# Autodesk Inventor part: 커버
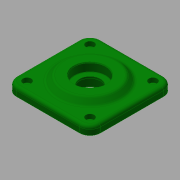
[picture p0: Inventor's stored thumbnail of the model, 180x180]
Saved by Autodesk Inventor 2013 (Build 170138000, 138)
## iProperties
Created: 2016-05
Part Number: 커버
Document SubType Name: Modeling
Designer: mduedu
Density: 2.71 g/cm^3
Material: 알루미늄 6061
Author: mduedu
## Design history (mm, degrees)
sketch "스케치1"
  geometry: L1 (-40, -40)-(40, -40); L2 (40, -40)-(40, 40); L3 (40, 40)-(-40, 40); L4 (-40, 40)-(-40, -40); L5 (-40, -40)-(40, 40); L6 (40, -40)-(-40, 40); C1 r 25 at (0, 0); 1 further point
  constraints: 12 end point, 2 midpoint, 2 parallel, 1 centre point, 1 coincident, 1 horizontal, 1 perpendicular
  dimensions: "d30" = 50 diameter of C1; "d33" = 80 distance of L3.end L2.end; "d34" = 80 distance of L2.end L1.end
extrude "돌출1" new body sketch "스케치1" distance "d0" = 8; taper "d1" = 0 deg
fillet "모깎기4" dims "d35" = 10
extrude "돌출2" join sketch "스케치1" distance "d2" = 12; taper "d3" = 0 deg
sketch "스케치2"
  geometry: C1 r 30 at (0, 0); 1 further point
  constraints: 1 centre point, 1 coincident
  dimensions: "d4" = 60 diameter of C1
extrude "돌출3" join sketch "스케치2" distance "d5" = 5; taper "d6" = -45 deg
sketch "스케치3"
  geometry: L1 (30, -40)-(-30, -40) reference; L2 (40, 30)-(40, -30) reference; L3 (-30, 40)-(30, 40) reference; L4 (-40, -30)-(-40, 30) reference; C1 r 30 at (0, 0) reference; A1 r 10 centre (-30, -30) between (-40, -30) and (-30, -40) reference; A2 r 10 centre (30, -30) between (30, -40) and (40, -30) reference; A3 r 10 centre (30, 30) between (40, 30) and (30, 40) reference; A4 r 10 centre (-30, 30) between (-30, 40) and (-40, 30) reference; 4 further points
  constraints: 4 coincident
hole "구멍2" sketch "스케치3" at (-30, 30), (30, 30), (30, -30), (-30, -30) diameter "d36" = 4.5; stored, may be unused: countersink angle "d40" = 90 deg, drill point angle "d42" = 118 deg; dims "d37" = 6, "d38" = 8, "d39" = 4.4, "d41" = 8
fillet "모깎기1" dims "d14" = 3
fillet "모깎기5" dims "d43" = 3
sketch "스케치4"
  geometry: L1 (-23.757, 13)-(23.757, 13) reference; L2 (25, -12)-(-25, -12) reference; L3 (0, -12)-(0, 13); L4 (-20, -12)-(-20, 0); L5 (-20, 0)-(-15, 0); L6 (-15, 0)-(-15, 3); L7 (-15, 3)-(-10, 3); L8 (-10, 3)-(-10, 4.7); L9 (-10, 4.7)-(-15, 4.7); L10 (-15, 4.7)-(-15, 13); 1 further point
  constraints: 16 end point, 6 parallel, 2 midpoint, 2 point on line, 1 perpendicular
  dimensions: "d15" = 40 diameter of L4 L3; "d16" = 30 diameter of L10 L3; "d17" = 8.3 distance of L9.end L10.end; "d18" = 12 distance of L4.start L4.end; "d19" = 3 distance of L5.end L6.end; "d20" = 30 diameter of L6 L3; "d21" = 20 diameter of L8 L3
revolve "회전1" sketch "스케치4" stored, may be unused: angle "d22" = 90 deg
fillet "모깎기2" dims "d23" = 3
fillet "모깎기3" dims "d24" = 0.3
chamfer "모따기1" distance "d25" = 1; stored, may be unused: second distance "d26" = 2, angle "d27" = 45 deg
chamfer "모따기2" distance "d44" = 0.8; stored, may be unused: second distance "d45" = 2, angle "d46" = 30 deg
node "솔리드1"
node "투영된 루프1"
